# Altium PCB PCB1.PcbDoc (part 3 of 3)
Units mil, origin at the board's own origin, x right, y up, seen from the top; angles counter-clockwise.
Board outline 6299 x 3937 mil, 12 copper layers (TopLayer, VCC, GROUND, MidLayer1, MidLayer2, MidLayer3, MidLayer4, MidLayer5, MidLayer6, MidLayer7, MidLayer8, BottomLayer); 299 components, 467 nets, 2148 pads, 429 vias.
Unrouted connection lines stored in the file: 461.
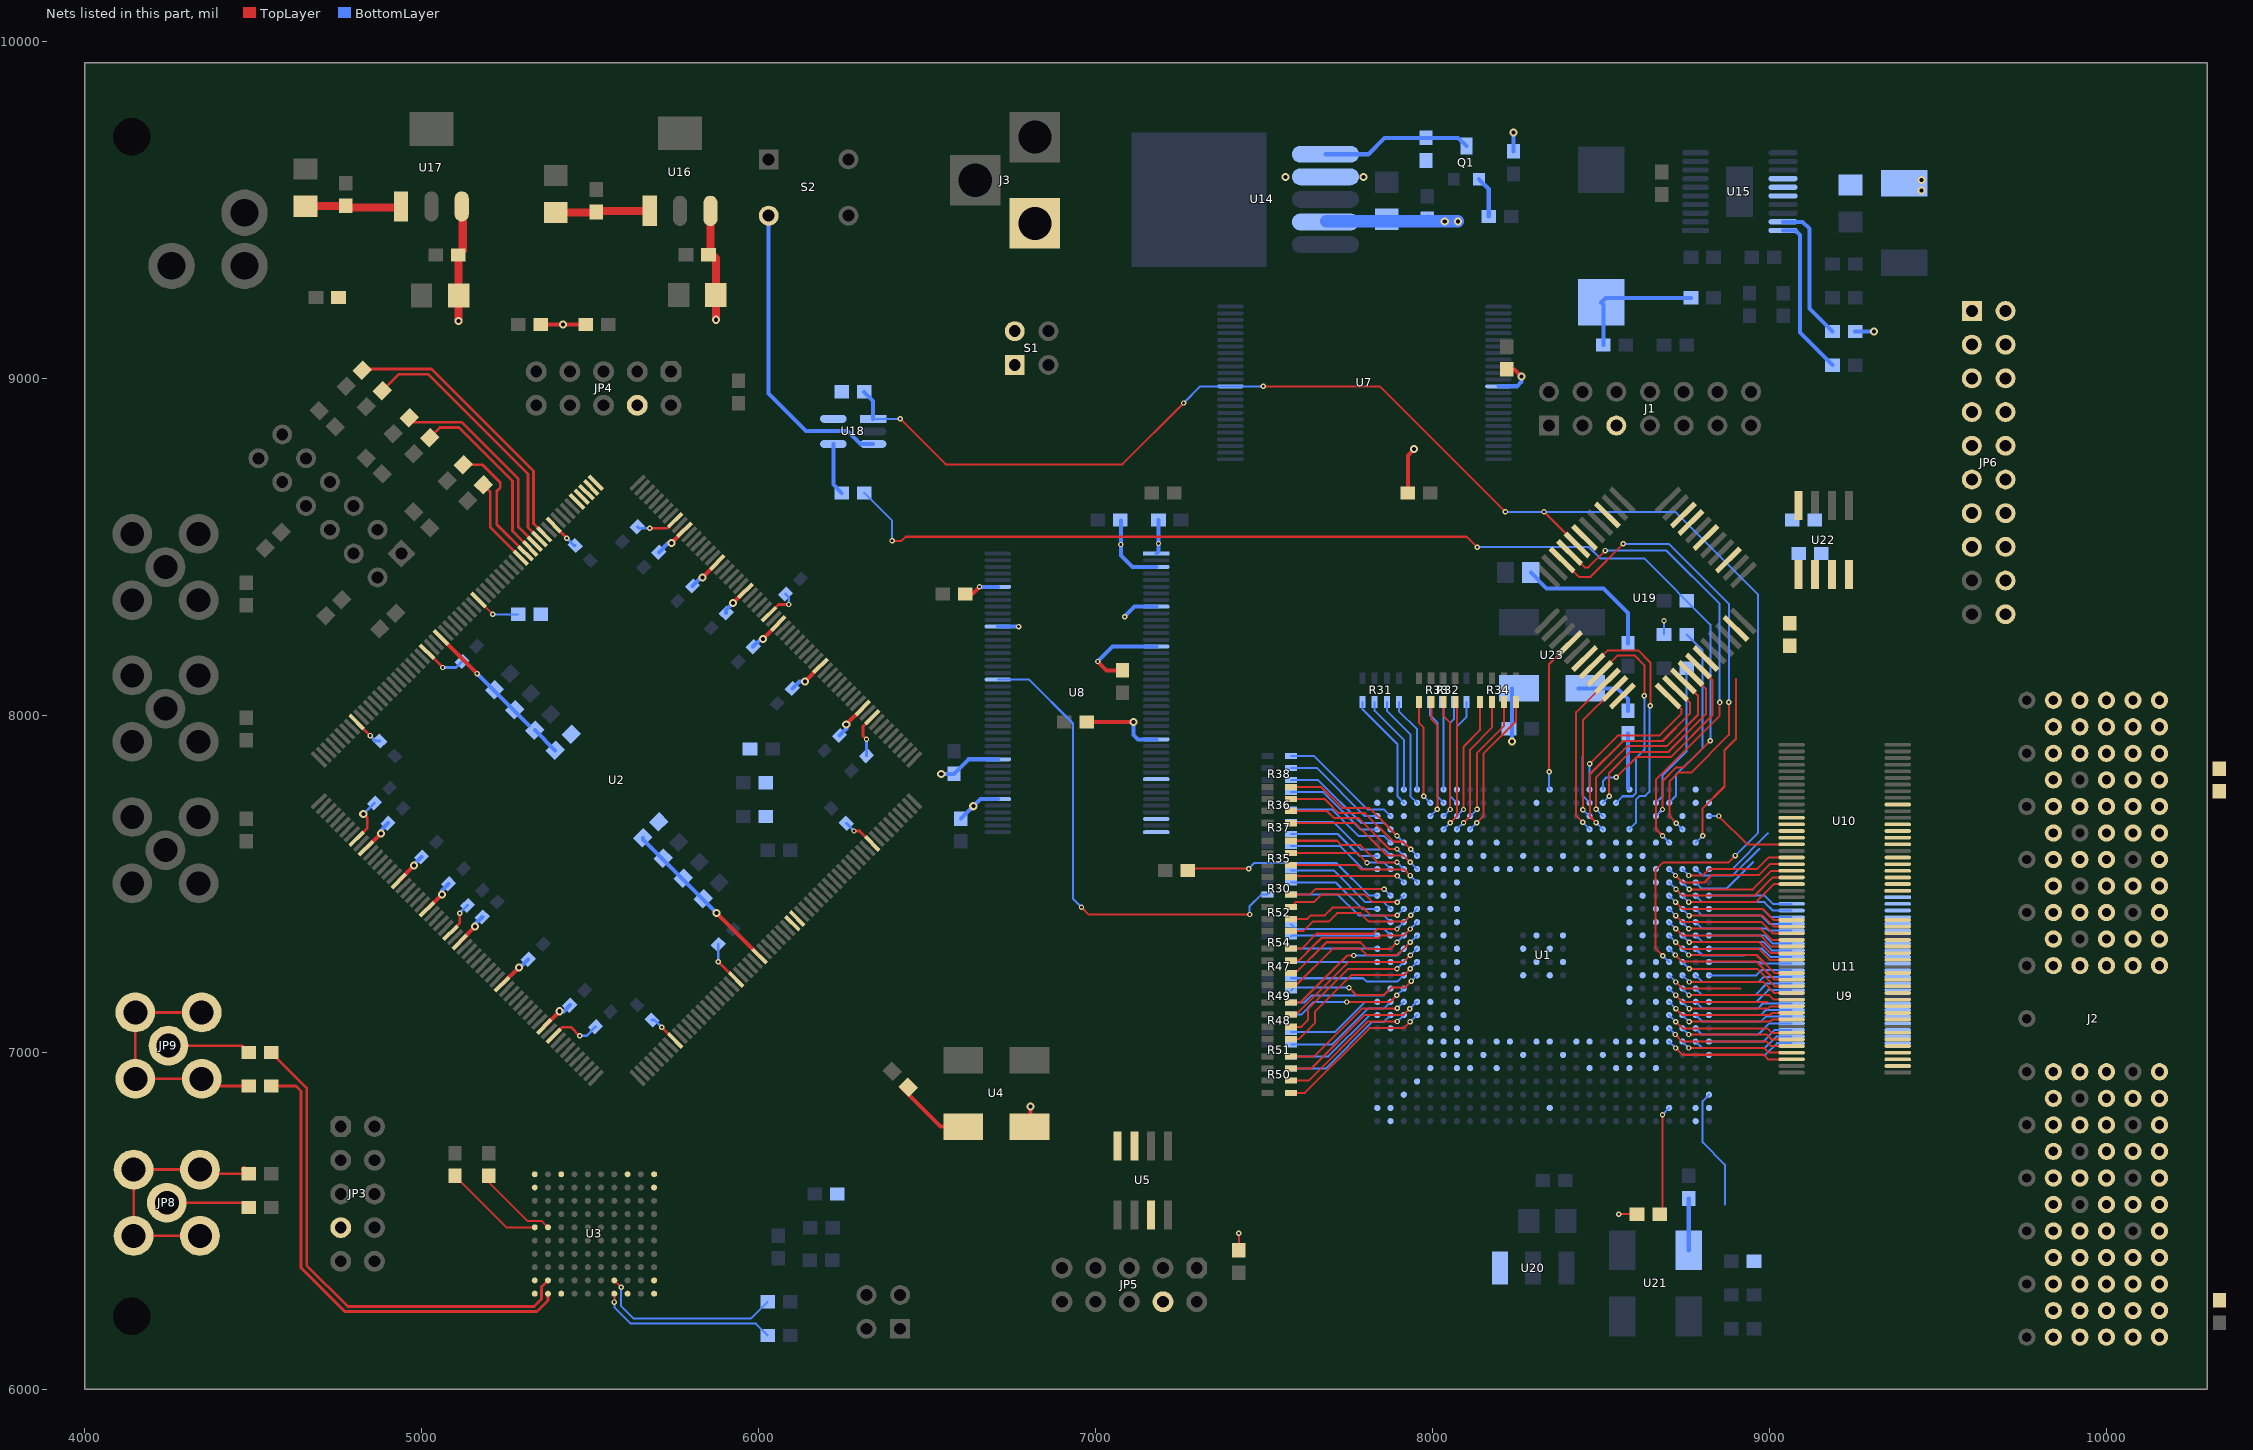
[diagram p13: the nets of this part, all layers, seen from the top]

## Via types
v1: diameter 16, hole 8, TopLayer to BottomLayer, 343 vias
v2: diameter 24, hole 12, TopLayer to BottomLayer, 84 vias
v3: diameter 56.69, hole 56.69, TopLayer to BottomLayer, 2 vias

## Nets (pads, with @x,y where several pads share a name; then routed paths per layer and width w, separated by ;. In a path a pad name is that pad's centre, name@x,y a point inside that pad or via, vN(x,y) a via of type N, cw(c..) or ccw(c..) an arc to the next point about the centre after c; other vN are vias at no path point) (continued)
NetDS3_2: DS3.2 R19.1
NetDS4_2: DS4.2 R20.1
NetDS5_2: DS5.2 R21.1
NetDS6_1: DS6.1 R62.1
NetDS7_1: DS7.1 R63.1
NetDS9_1: DS9.1 R86.2 | length 428.8
  BottomLayer w12: DS9.1@8291.4,8424 8338.4,8377 8507,8377 8580,8304 R86.2@8580,8213.46
NetQ1_1: Q1.1 R73.1 U14.1 | length 448.1
  BottomLayer w12: U14.1@7682,9665 7809,9665 7857.46,9713.46 8075.75,9713.46 Q1.1@8100,9689.21
NetQ1_2: Q1.2 R72.1 | length 124.8
  BottomLayer w12: Q1.2@8137.4,9590.79 8166.54,9561.65 R72.1@8166.54,9480 R72.1@8167.91,9481.37
NetR2_2: R2.2 U2.133 | length 781.9
  TopLayer w8: R2.2@4883.66,8963.66 4932,9012 5020,9012 5316,8716 5316,8557.18 U2.133@5350.03,8523.15
NetR3_2: R3.2 U2.132 | length 836.8
  TopLayer w8: R3.2@4823.66,9023.66 4828,9028 5029,9028 5332,8725 5332,8569.02 U2.132@5363.94,8537.07
NetR5_2: R5.2 U2.135 | length 546.1
  TopLayer w8: R5.2@5023.66,8823.66 5054,8854 5111,8854 5270,8695 5270,8547.5 U2.135@5322.19,8495.32
NetR6_2: R6.2 U2.134 | length 611.7
  TopLayer w8: R6.2@4963.66,8883.66 4977.33,8870 5119,8870 5287,8702 5287,8558.34 U2.134@5336.11,8509.24
NetR9_2: R9.2 U2.137 | length 262
  TopLayer w8: R9.2@5183.66,8683.66 5204,8663.33 5204,8557.82 U2.137@5294.35,8467.48
NetR10_2: R10.2 U2.136 | length 380.6
  TopLayer w8: R10.2@5123.66,8743.66 5181,8743.66 5233,8691.66 5233,8675 5223,8665 5223,8566.66 U2.136@5308.27,8481.4
NetR12_1: R12.1 U3.F9 | length 250.1
  TopLayer w6: R12.1@5199,6633.54 5199,6615 5315,6499 5356.89,6499 U3.F9@5375.04,6480.85
NetR13_1: R13.1 U3.F10 | length 299.9
  TopLayer w6: R13.1@5099,6633.54 5251.69,6480.85 U3.F10@5335.67,6480.85
NetR22_2: R22.2 U2.34
NetR23_2: R23.2 U2.35
NetR24_1: R24.1 U4.3 | length 231.7
  TopLayer w12: R24.1@6423.66,6896.34 6540,6780 U4.3@6607.15,6780
NetR25_1: R25.1 U6.3
NetR30_1: R30.1 U1.K25 | length 342.5
  BottomLayer w6: R30.1@7580,7540 7706.06,7540 7800.2,7445.87 7854.92,7445.87 U1.K25@7875.12,7425.67
NetR30_2: R30.2 U1.K26 | length 288.2
  BottomLayer w6: R30.2@7580,7504 7712.54,7504 7790.87,7425.67 U1.K26@7835.75,7425.67
NetR30_3: R30.3 U1.L25 | length 329
  BottomLayer w6: R30.3@7580,7468 7719.01,7468 7780.51,7406.5 7854.92,7406.5 U1.L25@7875.12,7386.3
NetR31_1: R31.1 U1.A23 | length 282.3
  BottomLayer w6: R31.1@7900,8040 7900,8012.4 7953.86,7958.54 U1.A23@7953.86,7780
NetR31_2: R31.2 U1.B23 | length 336.6
  BottomLayer w6: R31.2@7864,8040 7864,8013.95 7934.06,7943.9 7934.06,7760.43 U1.B23@7953.86,7740.63
NetR31_3: R31.3 U1.A24 | length 295.8
  BottomLayer w6: R31.3@7828,8040 7828,8013.54 7914.49,7927.05 U1.A24@7914.49,7780
NetR31_4: R31.4 U1.B24 | length 350.1
  BottomLayer w6: R31.4@7792,8040 7792,8018.04 7895.67,7914.37 7895.67,7759.45 U1.B24@7914.49,7740.63
NetR32_1: R32.1 U1.A20 | length 271.6
  BottomLayer w6: U1.A20@8071.97,7780 8071.97,7966.65 8100,7994.69 R32.1@8100,8040
NetR32_2: R32.2 U1.B20 | length 312.5
  BottomLayer w6: R32.2@8064,8040 8064,7990.18 8052.17,7978.35 8052.17,7760.43 U1.B20@8071.97,7740.63
NetR32_3: R32.3 U1.A21 | length 261.9
  BottomLayer w6: R32.3@8028,8040 8032.6,8035.4 U1.A21@8032.6,7780
NetR32_4: R32.4 U1.B21 | length 316.2
  BottomLayer w6: R32.4@7992,8040 7992,8001.11 8013.78,7979.33 8013.78,7759.45 U1.B21@8032.6,7740.63
NetR33_1: R33.1 U1.B22 | length 313.1
  TopLayer w6: R33.1@7960,8040 7960,7977.01 7973.43,7963.58 v1(7973.43,7760.43)
  BottomLayer w6: v1(7973.43,7760.43) U1.B22@7993.23,7740.63
NetR33_2: R33.2 U1.C22 | length 354.6
  TopLayer w6: R33.2@7996,8040 7996,7988.25 8013.78,7970.47 v1(8013.78,7721.81)
  BottomLayer w6: U1.C22@7993.23,7701.26 v1(8013.78,7721.81)
NetR33_3: R33.3 U1.C21 | length 355.2
  TopLayer w6: R33.3@8032,8040 8032,7998.51 8052.17,7978.35 v1(8052.17,7720.83)
  BottomLayer w6: U1.C21@8032.6,7701.26 v1(8052.17,7720.83)
NetR33_4: R33.4 U1.D21 | length 396
  TopLayer w6: v1(8052.17,7681.46) 8071.85,7701.14 8071.85,8036.15 R33.4@8068,8040
  BottomLayer w6: U1.D21@8032.6,7661.89 v1(8052.17,7681.46)
NetR34_1: R34.1 U1.C20 | length 366.9
  TopLayer w6: v1(8091.54,7720.83) 8091.54,7907.48 8140,7955.94 R34.1@8140,8040
  BottomLayer w6: U1.C20@8071.97,7701.26 v1(8091.54,7720.83)
NetR34_2: R34.2 U1.D20 | length 421.2
  TopLayer w6: v1(8091.54,7681.46) 8111.22,7701.14 8111.22,7898.62 8176,7963.4 R34.2@8176,8040
  BottomLayer w6: U1.D20@8071.97,7661.89 v1(8091.54,7681.46)
NetR34_3: R34.3 U1.C19 | length 380.4
  TopLayer w6: v1(8131.89,7721.81) 8131.89,7888.78 8212,7968.89 R34.3@8212,8040
  BottomLayer w6: U1.C19@8111.34,7701.26 v1(8131.89,7721.81)
NetR34_4: R34.4 U1.D19 | length 434.7
  TopLayer w6: v1(8130.91,7681.46) 8150.59,7701.14 8150.59,7885.83 8248,7983.24 R34.4@8248,8040
  BottomLayer w6: U1.D19@8111.34,7661.89 v1(8130.91,7681.46)
NetR35_1: R35.1 U1.H24 | length 343.9
  TopLayer w6: R35.1@7580,7520 7583.62,7523.62 v1(7895.27,7523.62)
  BottomLayer w6: v1(7895.27,7523.62) U1.H24@7914.49,7504.41
NetR35_2: R35.2 U1.H23 | length 395.2
  TopLayer w6: R35.2@7580,7556 7774.71,7556 7787.4,7543.31 7914.96,7543.31 v1(7933.66,7524.61)
  BottomLayer w6: v1(7933.66,7524.61) U1.H23@7953.86,7504.41
NetR35_3: R35.3 U1.G25 | length 315.1
  TopLayer w6: R35.3@7580,7592 7776.11,7592 v1(7805.12,7562.99)
  BottomLayer w6: v1(7805.12,7562.99) 7855.9,7562.99 U1.G25@7875.12,7543.78
NetR35_4: R35.4 U1.G24 | length 369.4
  TopLayer w6: R35.4@7580,7628 7716.49,7628 7729.33,7615.16 7785.43,7615.16 7836.61,7563.98 v1(7894.29,7563.98)
  BottomLayer w6: v1(7894.29,7563.98) U1.G24@7914.49,7543.78
NetR36_1: R36.1 U1.G23 | length 430.3
  TopLayer w6: R36.1@7580,7680 7769.8,7680 7866.14,7583.66 7913.98,7583.66 v1(7933.66,7563.98)
  BottomLayer w6: v1(7933.66,7563.98) U1.G23@7953.86,7543.78
NetR36_2: R36.2 U1.F24 | length 389.5
  TopLayer w6: R36.2@7580,7716 7686.56,7716 7707.52,7695.04 7780.36,7695.04 7872.05,7603.35 v1(7894.29,7603.35)
  BottomLayer w6: v1(7894.29,7603.35) U1.F24@7914.49,7583.15
NetR36_3: R36.3 U1.F23 | length 443.8
  TopLayer w6: R36.3@7580,7752 7679.1,7752 7721.46,7709.65 7799.21,7709.65 7883.86,7625 7912.01,7625 v1(7934.65,7602.36)
  BottomLayer w6: v1(7934.65,7602.36) U1.F23@7953.86,7583.15
NetR36_4: R36.4 U1.E24 | length 402.9
  TopLayer w6: R36.4@7580,7788 7668.69,7788 7723.97,7732.73 7731.38,7725.31 ; 7731.56,7725.49 7811.51,7725.49 v1(7894.29,7642.72)
  BottomLayer w6: v1(7894.29,7642.72) U1.E24@7914.49,7622.52
NetR37_1: R37.1 U1.E25 | length 335.5
  BottomLayer w6: R37.1@7580,7720 7702.24,7720 7780.51,7641.73 7855.9,7641.73 U1.E25@7875.12,7622.52
NetR37_2: R37.2 U1.F25 | length 336.9
  BottomLayer w6: R37.2@7580,7684 7704.78,7684 7786.42,7602.36 7855.9,7602.36 U1.F25@7875.12,7583.15
NetR37_3: R37.3 U1.F26 | length 282.6
  BottomLayer w6: R37.3@7580,7648 7718.14,7648 7782.99,7583.15 U1.F26@7835.75,7583.15
NetR37_4: R37.4 U1.G26 | length 284
  BottomLayer w6: R37.4@7580,7612 7725.6,7612 7793.82,7543.78 U1.G26@7835.75,7543.78
NetR38_1: R38.1 U1.C25 | length 369.2
  BottomLayer w6: R38.1@7580,7880 7647.56,7880 7807.09,7720.47 7855.9,7720.47 U1.C25@7875.12,7701.26
NetR38_2: R38.2 U1.C26 | length 314.9
  BottomLayer w6: R38.2@7580,7844 7656,7844 7798.74,7701.26 U1.C26@7835.75,7701.26
NetR38_3: R38.3 U1.D25 | length 355.6
  BottomLayer w6: R38.3@7580,7808 7660.5,7808 7787.4,7681.1 7855.9,7681.1 U1.D25@7875.12,7661.89
NetR38_4: R38.4 U1.D26 | length 301.4
  BottomLayer w6: R38.4@7580,7772 7675.83,7772 7785.94,7661.89 U1.D26@7835.75,7661.89
NetR39_1: R39.1 U19.21
NetR40_1: R40.1 U19.30
NetR47_1: R47.1 U1.M23 | length 450.2
  TopLayer w6: R47.1@7580,7200 7595.67,7200 7703.74,7308.07 7785.43,7308.07 7804.13,7289.37 7896.3,7289.37 v1(7933.7,7326.77)
  BottomLayer w6: v1(7933.7,7326.77) U1.M23@7953.86,7346.93
NetR47_2: R47.2 U1.M24 | length 397.6
  TopLayer w6: R47.2@7580,7236 7594.27,7236 7685.04,7326.77 7785.43,7326.77 7806.1,7306.1 7873.66,7306.1 v1(7894.33,7326.77)
  BottomLayer w6: v1(7894.33,7326.77) U1.M24@7914.49,7346.93
NetR47_3: R47.3 U1.L23 | length 421.2
  TopLayer w6: R47.3@7580,7272 7602.71,7272 7646.57,7315.86 7670.19,7339.48 7839.48,7339.48 7846.46,7346.46 7914.02,7346.46 v1(7933.7,7366.14)
  BottomLayer w6: v1(7933.7,7366.14) U1.L23@7953.86,7386.3
NetR47_4: R47.4 U1.L24 | length 366.9
  TopLayer w6: R47.4@7580,7308 7611.15,7308 7655.15,7352 7822,7352 7836.14,7366.14 v1(7894.33,7366.14)
  BottomLayer w6: v1(7894.33,7366.14) U1.L24@7914.49,7386.3
NetR48_1: R48.1 U1.P23 | length 488.6
  TopLayer w6: R48.1@7580,7040 7603.98,7040 7650.59,7086.61 7650.59,7121.06 7758.86,7229.33 7915,7229.33 v1(7933.7,7248.03)
  BottomLayer w6: v1(7933.7,7248.03) U1.P23@7953.86,7268.19
NetR48_2: R48.2 U1.P24 | length 433.1
  TopLayer w6: R48.2@7580,7076 7610.45,7076 7629.92,7095.47 7629.92,7127.95 7750,7248.03 v1(7894.33,7248.03)
  BottomLayer w6: v1(7894.33,7248.03) U1.P24@7914.49,7268.19
NetR48_3: R48.3 U1.N23 | length 454.2
  TopLayer w6: R48.3@7580,7112 7594.28,7112 7750.98,7268.7 7914.37,7268.7 v1(7934.06,7288.39)
  BottomLayer w6: v1(7934.06,7288.39) U1.N23@7953.23,7307.56
NetR48_4: R48.4 U1.N24 | length 400.6
  TopLayer w6: R48.4@7580,7148 7607.65,7148 7747.05,7287.4 v1(7765.75,7287.4)
  BottomLayer w6: v1(7765.75,7287.4) 7894.33,7287.4 U1.N24@7914.49,7307.56
NetR49_1: R49.1 U1.R24 | length 346.7
  BottomLayer w6: R49.1@7580,7220 7793.78,7220 7804.13,7209.65 7895.31,7209.65 U1.R24@7914.49,7228.82
NetR49_2: R49.2 U1.R23 | length 410.4
  TopLayer w6: v1(7751.97,7191.93) 7773.62,7170.28 7855.31,7170.28 7876.97,7191.93 7916.97,7191.93 v1(7936.65,7211.61)
  BottomLayer w6: R49.2@7580,7184 7587.93,7191.93 v1(7751.97,7191.93) ; v1(7936.65,7211.61) U1.R23@7953.86,7228.82
NetR49_3: R49.3 U1.T25 | length 312.3
  BottomLayer w6: R49.3@7580,7148 7619.46,7148 7640.75,7169.29 7854.96,7169.29 U1.T25@7875.12,7189.45
NetR49_4: R49.4 U1.T24 | length 372.8
  TopLayer w6: v1(7745.08,7149.61) 7874.02,7149.61 v1(7893.7,7169.29)
  BottomLayer w6: R49.4@7580,7112 7610.03,7112 7647.64,7149.61 v1(7745.08,7149.61) ; v1(7893.7,7169.29) 7913.86,7189.45 U1.T24@7920.75,7189.45
NetR50_1: R50.1 U1.V23 | length 469.4
  TopLayer w6: R50.1@7580,6880 7621.14,6880 7812.99,7071.85 7914.37,7071.85 v1(7933.07,7090.55)
  BottomLayer w6: v1(7933.07,7090.55) 7953.23,7110.71 U1.V23@7953.86,7110.71
NetR50_2: R50.2 U1.V24 | length 415.1
  TopLayer w6: R50.2@7580,6916 7632.54,6916 7808.07,7091.54 v1(7895.31,7091.54)
  BottomLayer w6: v1(7895.31,7091.54) U1.V24@7914.49,7110.71
NetR50_3: R50.3 U1.U23 | length 455.9
  TopLayer w6: R50.3@7580,6952 7639.01,6952 7798.23,7111.22 7913.39,7111.22 v1(7932.09,7129.92)
  BottomLayer w6: v1(7932.09,7129.92) 7952.24,7150.08 U1.U23@7953.86,7150.08
NetR50_4: R50.4 U1.U24 | length 401.6
  TopLayer w6: R50.4@7580,6988 7648.43,6988 7791.34,7130.91 v1(7895.31,7130.91)
  BottomLayer w6: v1(7895.31,7130.91) U1.U24@7914.49,7150.08
NetR51_1: R51.1 U1.U26 | length 293.1
  BottomLayer w6: R51.1@7580,7060 7709.61,7060 7799.68,7150.08 U1.U26@7835.75,7150.08
NetR51_2: R51.2 U1.U25 | length 347.3
  BottomLayer w6: R51.2@7580,7024 7702.15,7024 7808.07,7129.92 7854.96,7129.92 U1.U25@7875.12,7150.08
NetR51_3: R51.3 U1.V26 | length 306.6
  BottomLayer w6: R51.3@7580,6988 7690.76,6988 7813.46,7110.71 U1.V26@7835.75,7110.71
NetR51_4: R51.4 U1.V25 | length 360.9
  BottomLayer w6: R51.4@7580,6952 7682.31,6952 7820.87,7090.55 7854.96,7090.55 U1.V25@7875.12,7110.71
NetR52_1: R52.1 U1.K23 | length 421.9
  TopLayer w6: R52.1@7580,7360 7615.91,7360 7643.7,7387.8 7691.8,7387.8 7717,7413 7785.8,7413 7811,7387.8 7915.98,7387.8 v1(7934.68,7406.5)
  BottomLayer w6: v1(7934.68,7406.5) U1.K23@7953.86,7425.67
NetR52_2: R52.2 U1.K24 | length 366.2
  TopLayer w6: R52.2@7580,7396 7628.28,7396 7638.78,7406.5 7680.5,7406.5 7704,7430 7793.5,7430 7817,7406.5 v1(7895.31,7406.5)
  BottomLayer w6: v1(7895.31,7406.5) U1.K24@7914.49,7425.67
NetR52_3: R52.3 U1.J24 | length 366.5
  TopLayer w6: R52.3@7580,7432 7593.87,7445.87 7647,7445.87 7669.13,7468 7799.87,7468 7822,7445.87 v1(7895.31,7445.87)
  BottomLayer w6: v1(7895.31,7445.87) U1.J24@7914.49,7465.04
NetR52_4: R52.4 U1.J25 | length 309.8
  TopLayer w6: R52.4@7580,7468 7635.75,7468 7652,7484.25 v1(7855.9,7484.25)
  BottomLayer w6: v1(7855.9,7484.25) U1.J25@7875.12,7465.04
NetR54_1: R54.1 U1.M25 | length 308.8
  BottomLayer w6: R54.1@7580,7380 7593.86,7366.14 7855.9,7366.14 U1.M25@7875.12,7346.93
NetR54_2: R54.2 U1.M26 | length 257
  BottomLayer w6: R54.2@7580,7344 7582.93,7346.93 U1.M26@7835.75,7346.93
NetR54_3: R54.3 U1.N26 | length 255.9
  BottomLayer w6: R54.3@7580,7308 7580.44,7307.56 U1.N26@7835.75,7307.56
NetR54_4: R54.4 U1.P26 | length 257.3
  BottomLayer w6: R54.4@7580,7272 7583.81,7268.19 U1.P26@7835.75,7268.19
NetR55_1: R55.1 U1.J26 | length 611.5
  TopLayer w6: R55.1@7273.46,7540 7278.46,7545 v1(7454,7545)
  BottomLayer w6: v1(7454,7545) 7470.93,7561.93 7714.65,7561.93 7811.54,7465.04 U1.J26@7835.75,7465.04
NetR56_2: R56.2 S1.1
NetR57_2: R57.2 S1.2
NetR65_2: R65.2 U15.20 | length 481.9
  BottomLayer w12: U15.20@9039.84,9439 9076,9439 9090,9425 9090,9135.54 R65.2@9186.54,9039
NetR66_1: R66.1 U15.19 | length 420.1
  BottomLayer w12: U15.19@9039.84,9464.59 9097.41,9464.59 9118,9444 9118,9207.54 R66.1@9186.54,9139
NetR76_1: R76.1 U23.3 | length 194.9
  BottomLayer w12: U23.3@8432.85,8080 8548,8080 8580,8048 R76.1@8580,8013.46
NetR79_2: R79.2 U1.B4 | length 560.1
  BottomLayer w6: U1.B4@8701.89,7740.63 8722,7760.74 8722,7824 8801,7903 8801,8192.46 R79.2@8753.46,8240
NetR80_1: R80.1 U1.AE4 | length 326.9
  TopLayer w6: R80.1@8673.46,6520 8682,6528.54 v1(8682,6815.23)
  BottomLayer w6: v1(8682,6815.23) U1.AE4@8701.89,6835.12
NetR81_1: R81.1 U18.4 | length 155.4
  BottomLayer w12: U18.4@6221.89,8805.2 6221.89,8684.65 R81.1@6246.54,8660
NetR81_2: R81.2 R83.2 U1.C5 | length 3365.1
  TopLayer w6: v1(6396,8518) 6424,8518 6436,8530 8101,8530 v1(8132,8499) ; v1(8682,7720.74) 8682,7805 8722,7845 8744,7845 v1(8824,7925)
  BottomLayer w6: R81.2@6313.46,8660 6396,8577.46 v1(6396,8518) ; v1(8132,8499) 8464,8499 8497,8466 8627.46,8466 8824,8269.46 v1(8824,7925) ; U1.C5@8662.52,7701.26 v1(8682,7720.74)
NetR82_1: R82.1 U21.3 | length 153.7
  BottomLayer w12: U21.3@8760,6412.85 R82.1@8760,6566.54
NetR84_2: R84.2 U1.B5 | length 437
  BottomLayer w6: U1.B5@8662.52,7740.63 8682,7760.11 8682,7822 8753.46,7893.46 R84.2@8753.46,8140
NetS2_2: S2.2 U18.3 | length 899.7
  BottomLayer w12: S2.2@6030,9482.68 6030,8955 6141,8844 6264,8844 6302.8,8805.2 U18.3@6340,8805.2
NSTATUS: R29.1 U2.146 | length 134.9
  TopLayer w6: U2.146@5169.07,8342.2 v1(5211.27,8300)
  BottomLayer w6: v1(5211.27,8300) R29.1@5286.54,8300
OUT1+: C3.1 U3.B9 | length 1495.6
  TopLayer w8: C3.1@4553.46,7000 4659,6894.46 4659,6368 4781,6246 5334,6246 5356,6268 5356,6304.33 U3.B9@5375.04,6323.37
OUT1-: C4.1 U3.A9 | length 1439.3
  TopLayer w8: C4.1@4553.46,6900 4627,6900 4642,6885 4642,6361 4772,6231 5342,6231 5375.04,6264.04 U3.A9@5375.04,6284
OUT2+: C28.2 U3.A4 | length 529.4
  TopLayer w6: v1(5571.89,6259.11) U3.A4@5571.89,6284
  BottomLayer w6: v1(5571.89,6259.11) 5571.89,6244.11 5621,6195 5991.54,6195 C28.2@6026.54,6160
OUT2-: C27.2 U3.B4 | length 555.3
  TopLayer w6: U3.B4@5571.89,6323.37 v1(5592,6303.26)
  BottomLayer w6: v1(5592,6303.26) 5592,6247 5629.04,6209.96 5976.49,6209.96 C27.2@6026.54,6260
P\C\I\6\6\: R74.1 U1.AD1 | length 360.7
  BottomLayer w6: U1.AD1@8820,6874.49 8801,6855.49 8801,6733 8867,6667 8867,6549
P_AD0: U1.Y3 U9.45 | length 337.4
  TopLayer w6: v1(8760.23,7013) 8984,7013 8997.94,6999.06 U9.45@9065.04,6999.06
  BottomLayer w6: U1.Y3@8741.26,7031.97 v1(8760.23,7013)
P_AD1: U1.AA1 U11.25 | length 259.4
  BottomLayer w6: U1.AA1@8820,6992.6 8987.6,6992.6 9022.25,7027.24 U11.25@9065.04,7027.24
P_AD2: U1.Y4 U9.46 | length 384.9
  TopLayer w6: v1(8720.86,7013) 8740.86,6993 8982,6993 8995.63,6979.37 U9.46@9065.04,6979.37
  BottomLayer w6: U1.Y4@8701.89,7031.97 v1(8720.86,7013)
P_AD3: U1.Y2 U11.26 | length 306.3
  BottomLayer w6: U1.Y2@8780.63,7031.97 8799.6,7013 8986,7013 9019.93,7046.93 U11.26@9065.04,7046.93
P_AD4: U1.W3 U9.43 | length 337.4
  TopLayer w6: v1(8759.6,7053) 8991,7053 9005.58,7038.43 U9.43@9065.04,7038.43
  BottomLayer w6: U1.W3@8741.26,7071.34 v1(8759.6,7053)
P_AD5: U1.Y1 U11.27 | length 259.4
  BottomLayer w6: U1.Y1@8820,7031.97 8980.97,7031.97 9015.61,7066.61 U11.27@9065.04,7066.61
P_AD6: U1.W4 U9.44 | length 384.9
  TopLayer w6: v1(8720.23,7053) 8741.23,7032 8991,7032 9004.26,7018.74 U9.44@9065.04,7018.74
  BottomLayer w6: U1.W4@8701.89,7071.34 v1(8720.23,7053)
P_AD7: U1.W2 U11.28 | length 305.8
  BottomLayer w6: U1.W2@8780.63,7071.34 8798.97,7053 8966,7053 8999.3,7086.3 U11.28@9065.04,7086.3
P_AD8: U1.V2 U11.29 | length 298
  BottomLayer w6: U1.V2@8780.63,7110.71 8799.34,7092 8975,7092 8988.99,7105.98 U11.29@9065.04,7105.98
P_AD9: U1.V3 U9.40 | length 334.6
  TopLayer w6: v1(8760.97,7091) 9001,7091 9007.48,7097.48 U9.40@9065.04,7097.48
  BottomLayer w6: U1.V3@8741.26,7110.71 v1(8760.97,7091)
P_AD10: U1.V1 U11.30 | length 251.2
  BottomLayer w6: U1.V1@8820,7110.71 8973.71,7110.71 8988.67,7125.67 U11.30@9065.04,7125.67
P_AD11: U1.U4 U9.39 | length 381.9
  TopLayer w6: v1(8721.97,7130) 8740.97,7111 9001,7111 9007.17,7117.16 U9.39@9065.04,7117.16
  BottomLayer w6: U1.U4@8701.89,7150.08 v1(8721.97,7130)
P_AD12: U1.U2 U11.31 | length 299.1
  BottomLayer w6: U1.U2@8780.63,7150.08 8800.71,7130 8965,7130 8980.35,7145.35 U11.31@9065.04,7145.35
P_AD13: U1.U3 U9.38 | length 334.9
  TopLayer w6: v1(8761.34,7130) 8995,7130 9001.85,7136.85 U9.38@9065.04,7136.85
  BottomLayer w6: U1.U3@8741.26,7150.08 v1(8761.34,7130)
P_AD14: U1.U1 U11.33 | length 259.4
  BottomLayer w6: U1.U1@8820,7150.08 8961.08,7150.08 8995.73,7184.73 U11.33@9065.04,7184.73
P_AD15: U1.T3 U9.37 | length 337.4
  TopLayer w6: v1(8760.71,7170) 8999,7170 9012.47,7156.53 U9.37@9065.04,7156.53
  BottomLayer w6: U1.T3@8741.26,7189.45 v1(8760.71,7170)
P_AD16: U1.M3 U9.30 | length 345.6
  TopLayer w6: v1(8761.19,7327) 8970,7327 9002.67,7294.33 U9.30@9065.04,7294.33
  BottomLayer w6: U1.M3@8741.26,7346.93 v1(8761.19,7327)
P_AD17: U1.M2 U11.39 | length 302.7
  BottomLayer w6: U1.M2@8780.63,7346.93 8799.56,7328 8981,7328 9006.17,7302.84 U11.39@9065.04,7302.84
P_AD18: U1.M4 U9.31 | length 393.1
  TopLayer w6: v1(8721.82,7327) 8741.82,7307 8968,7307 9000.35,7274.65 U9.31@9065.04,7274.65
  BottomLayer w6: U1.M4@8701.89,7346.93 v1(8721.82,7327)
P_AD19: U1.L2 U11.42 | length 294.5
  BottomLayer w6: U1.L2@8780.63,7386.3 8798.93,7368 8990,7368 8996.11,7361.89 U11.42@9065.04,7361.89
P_AD20: U1.L3 U9.28 | length 345.6
  TopLayer w6: v1(8760.56,7367) 8973,7367 9006.3,7333.7 U9.28@9065.04,7333.7
  BottomLayer w6: U1.L3@8741.26,7386.3 v1(8760.56,7367)
P_AD21: U1.K2 U11.43 | length 302.7
  BottomLayer w6: U1.K2@8780.63,7425.67 8800.3,7406 8975,7406 8999.42,7381.57 U11.43@9065.04,7381.57
P_AD22: U1.L4 U9.29 | length 393.1
  TopLayer w6: v1(8721.19,7367) 8741.19,7347 8972,7347 9004.99,7314.02 U9.29@9065.04,7314.02
  BottomLayer w6: U1.L4@8701.89,7386.3 v1(8721.19,7367)
P_AD23: U1.K1 U11.44 | length 255.1
  BottomLayer w6: U1.K1@8820,7425.67 8978.33,7425.67 9002.74,7401.26 U11.44@9065.04,7401.26
P_AD24: U1.K4 U9.27 | length 393.1
  TopLayer w6: v1(8721.56,7406) 8740.56,7387 8975,7387 9008.61,7353.39 U9.27@9065.04,7353.39
  BottomLayer w6: U1.K4@8701.89,7425.67 v1(8721.56,7406)
P_AD25: U1.J1 U11.46 | length 255.2
  BottomLayer w6: U1.J1@8820,7465.04 8984.96,7465.04 9009.37,7440.63 U11.46@9065.04,7440.63
P_AD26: U1.J3 U10.46 | length 353.8
  TopLayer w6: v1(8760.3,7446) 8959,7446 9012.37,7499.37 U10.46@9065.04,7499.37
  BottomLayer w6: U1.J3@8741.26,7465.04 v1(8760.3,7446)
P_AD27: U1.H2 U10.36 | length 210.7
  BottomLayer w6: U1.H2@8780.63,7504.41 8799.04,7486 8872,7486 8951,7565
P_AD28: U1.J4 U9.25 | length 393.1
  TopLayer w6: v1(8720.93,7446) 8740.93,7426 8979,7426 9012.25,7392.76 U9.25@9065.04,7392.76
  BottomLayer w6: U1.J4@8701.89,7465.04 v1(8720.93,7446)
P_AD29: U1.G2 U10.37 | length 229.9
  BottomLayer w6: U1.G2@8780.63,7543.78 8799.41,7525 8891,7525 8970,7604
P_AD30: U1.H3 U10.44 | length 354.9
  TopLayer w6: v1(8761.67,7484) 8950,7484 9004.74,7538.74 U10.44@9065.04,7538.74
  BottomLayer w6: U1.H3@8741.26,7504.41 v1(8761.67,7484)
P_AD31: U1.G1 U10.38 | length 219
  BottomLayer w6: U1.G1@8820,7543.78 8888.78,7543.78 8995,7650
P_CBE0: U1.V4 U9.42 | length 384.9
  TopLayer w6: v1(8721.6,7091) 8741.6,7071 8993,7071 9005.89,7058.11 U9.42@9065.04,7058.11
  BottomLayer w6: U1.V4@8701.89,7110.71 v1(8721.6,7091)
P_CBE1: U1.T2 U11.34 | length 306.7
  BottomLayer w6: U1.T2@8780.63,7189.45 8800.08,7170 8957,7170 8991.41,7204.41 U11.34@9065.04,7204.41
P_CBE2: U1.M1 U11.40 | length 255.1
  BottomLayer w6: U1.M1@8820,7346.93 8985.07,7346.93 9009.48,7322.52 U11.40@9065.04,7322.52
P_CBE3: U1.J2 U11.45 | length 302.7
  BottomLayer w6: U1.J2@8780.63,7465.04 8799.67,7446 8984,7446 9009.06,7420.94 U11.45@9065.04,7420.94
P_CLK: U1.C1 U10.40 | length 279.7
  TopLayer w6: v1(8849.26,7701.26) 8933.04,7617.48 U10.40@9065.04,7617.48
  BottomLayer w6: U1.C1@8820,7701.26 v1(8849.26,7701.26)
P_DEVSEL: U1.P1 U11.37 | length 247
  BottomLayer w6: U1.P1@8820,7268.19 8971,7268.19 8975.72,7263.47 U11.37@9065.04,7263.47
P_EN: R61.1 U1.E2 | length 534.9
  TopLayer w6: v1(8801.11,7643) 8801.11,7724.11 8866,7789 8866,7896 8900,7930 8900,8108
  BottomLayer w6: U1.E2@8780.63,7622.52 v1(8801.11,7643)
P_FRAME: U1.N4 U9.34 | length 401.2
  TopLayer w6: v1(8720.45,7289) 8740.45,7269 8961,7269 9014.41,7215.59 U9.34@9065.04,7215.59
  BottomLayer w6: U1.N4@8701.89,7307.56 v1(8720.45,7289)
P_GNT: U1.H4 U10.45 | length 401.9
  TopLayer w6: v1(8722.3,7484) 8741.3,7465 8955,7465 9009.06,7519.06 U10.45@9065.04,7519.06
  BottomLayer w6: U1.H4@8701.89,7504.41 v1(8722.3,7484)
P_IDSEL: U1.K3 U9.26 | length 345.6
  TopLayer w6: v1(8760.93,7406) 8979,7406 9011.93,7373.07 U9.26@9065.04,7373.07
  BottomLayer w6: U1.K3@8741.26,7425.67 v1(8760.93,7406)
P_INTA: U1.G4 U10.43 | length 402.2
  TopLayer w6: v1(8720.67,7525) 8741.67,7504 8806,7504 8828.93,7526.93 8968.93,7526.93 9000.42,7558.43 U10.43@9065.04,7558.43
  BottomLayer w6: U1.G4@8701.89,7543.78 v1(8720.67,7525)
P_IRDY: U1.N1 U11.38 | length 255.1
  BottomLayer w6: U1.N1@8820,7307.56 8977.44,7307.56 9001.85,7283.15 U11.38@9065.04,7283.15
P_PAR: U1.P3 U9.35 | length 353.7
  TopLayer w6: v1(8761.45,7248) 8963,7248 9015.09,7195.9 U9.35@9065.04,7195.9
  BottomLayer w6: U1.P3@8741.26,7268.19 v1(8761.45,7248)
P_PERR: U1.R1 U11.36 | length 251.2
  BottomLayer w6: U1.R1@8820,7228.82 8960.82,7228.82 8975.78,7243.78 U11.36@9065.04,7243.78
P_REQ: U1.F1 U10.39
P_RST: U1.G3 U10.42 | length 353.6
  TopLayer w6: v1(8760.04,7525) 8802,7525 8821,7544 8962,7544 8996.11,7578.11 U10.42@9065.04,7578.11
  BottomLayer w6: U1.G3@8741.26,7543.78 v1(8760.04,7525)
P_SERR: U1.R2 U11.35 | length 298.9
  BottomLayer w6: U1.R2@8780.63,7228.82 8800.45,7209 8968,7209 8983.09,7224.1 U11.35@9065.04,7224.1
P_STOP: U1.R3 U9.36 | length 345.6
  TopLayer w6: v1(8761.08,7209) 8981,7209 9013.78,7176.22 U9.36@9065.04,7176.22
  BottomLayer w6: U1.R3@8741.26,7228.82 v1(8761.08,7209)
P_TRDY: U1.N3 U9.33 | length 353.7
  TopLayer w6: v1(8759.82,7289) 8961,7289 9014.73,7235.27 U9.33@9065.04,7235.27
  BottomLayer w6: U1.N3@8741.26,7307.56 v1(8759.82,7289)
PCI_EEAI: R78.1 U1.L5
PXI_3.3V: J2.B25 J2.C6 J2.C10 J2.C18 J2.C22 J2.E15 J2.E17 J2.E19 J2.E21 J2.E23
PXI_5V: J2.A1 J2.A25 J2.B3 J2.B23 J2.D2 J2.D24 J2.E1 J2.E25
PXI_+12V: J2.B1
PXI_-12V: J2.D1
PXI_ACK64#: J2.A24 JP6.9
PXI_AD0: J2.B24 U9.3
PXI_AD1: J2.E24 U11.24
PXI_AD2: J2.A23 U9.2
PXI_AD3: J2.C23 U11.23
PXI_AD4: J2.D23 U9.5
PXI_AD5: J2.A22 U11.22
PXI_AD6: J2.B22 U9.4
PXI_AD7: J2.E22 U11.21
PXI_AD8: J2.C21 U11.20
PXI_AD9: J2.D21 U9.7
PXI_AD10: J2.A20 U11.19
PXI_AD11: J2.B20 U9.9
PXI_AD12: J2.E20 U11.18
PXI_AD13: J2.A19 U9.10
PXI_AD14: J2.C19 U11.16
PXI_AD15: J2.D19 U9.11
PXI_AD16: J2.C11 U9.19
PXI_AD17: J2.D11 U11.9
PXI_AD18: J2.E11 U9.18
PXI_AD19: J2.A10 U11.6
PXI_AD20: J2.B10 U9.21
PXI_AD21: J2.E10 U11.5
PXI_AD22: J2.A9 U9.20
PXI_AD23: J2.C9 U11.4
PXI_AD24: J2.A8 U9.22
PXI_AD25: J2.B8 U11.2
PXI_AD26: J2.E8 U10.2
PXI_AD27: J2.A7 U10.12
PXI_AD28: J2.C7 U9.24
PXI_AD29: J2.D7 U10.11
PXI_AD30: J2.E7 U10.4
PXI_AD31: J2.A6 U10.10
PXI_BD_SEL#: J2.B15 JP6.5
PXI_BRSVP1A5: J2.E5
PXI_BRSVP1A6: JP6.2
PXI_BRSVP1B5: J2.D5
PXI_BRSVP1B6: JP6.12
PXI_C/BE0#: J2.A21 U9.6
PXI_C/BE1#: J2.A18 U11.14
PXI_C/BE2#: J2.A11 U11.7
PXI_C/BE3#: J2.E9 U11.3
PXI_DEVSEL#: J2.E16 U11.11
PXI_ENUM#: J2.C25 JP6.15
PXI_FRAME#: J2.D15 U9.14
PXI_GNT#: J2.A5 U10.3
PXI_HEALTHY#: J2.C1 J2.D4 JP6.14
PXI_IDSEL: J2.D9 U9.23
PXI_INTA#: J2.E3 U10.5
PXI_INTB#: J2.D3 JP6.16
PXI_INTC#: J2.C3 JP6.20
PXI_INTD#: J2.A3 JP6.13
PXI_INTP: J2.B4 JP6.3
PXI_INTS: J2.A4 JP6.11
PXI_IPMB_PWR: J2.E4 JP6.4
PXI_IPMB_SCL: J2.D17 JP6.10
PXI_IPMB_SDA: J2.C17 JP6.18
PXI_IRDY#: J2.C15 U11.10
PXI_LOCK#: J2.A16
PXI_M66EN: J2.B21 JP6.7 R60.2
PXI_PAR: J2.B18 U9.13
PXI_PCLK: J2.B6 U10.7
PXI_PERR#: J2.A17 U11.12
PXI_REQ64#: J2.D25 JP6.8
PXI_REQ#: J2.E6 U10.9
PXI_RST#: J2.C5 U10.6
PXI_SERR#: J2.E18 U11.13
PXI_STOP#: J2.B16 U9.12
PXI_TCK: J2.E2 JP6.6
PXI_TDIO: J2.A2 J2.B2
PXI_TMS: J2.C2 JP6.1
PXI_TRDY#: J2.A15 U9.16
PXI_VIO: J2.C4 J2.C8 J2.C16 J2.C20 J2.C24
SCL: R87.2 U1.E4 U19.41 | length 1352.2
  TopLayer w6: U19.41@8406.81,8483.22 8451.04,8439 8462,8439 v1(8512,8489) ; v1(8682,7642.41) 8663,7661.41 8663,7810 8851.61,7998.61 v1(8851.61,8038.42)
  BottomLayer w6: v1(8512,8489) 8694,8489 8851.61,8331.39 v1(8851.61,8038.42) ; v1(8682,7642.41) U1.E4@8701.89,7622.52
SDA: R88.2 U1.D3 U19.42 | length 1410.4
  TopLayer w6: U19.42@8384.54,8460.95 8435.49,8410 8467,8410 v1(8566,8509) ; v1(8723,7680.15) 8703,7700.15 8703,7804 8729,7830 8767,7830 8879,7942 v1(8879,8039)
  BottomLayer w6: v1(8566,8509) 8701,8509 8879,8331 v1(8879,8039) ; v1(8723,7680.15) U1.D3@8741.26,7661.89
SDCKE: R30.6 U8.67 | length 1432.1
  TopLayer w6: v1(6958,7431) 6980,7409 v1(7457,7409)
  BottomLayer w6: U8.67@6710,8105.98 6803.02,8105.98 6933,7976 6933,7456 v1(6958,7431) ; v1(7457,7409) 7457.25,7434.25 7491,7468 R30.6@7509.84,7468
SERIN+: C2.2 JP8.1 | length 248.3
  TopLayer w8: JP8.1@4244,6554 4472.54,6554 C2.2@4486.54,6540
SERIN-: C1.2 JP8.2 | length 757.4
  TopLayer w8: JP8.2@4342.43,6455.57 JP8.2@4145.57,6455.57 JP8.2@4145.57,6652.43 JP8.2@4342.43,6652.43 4354.85,6640 C1.2@4486.54,6640
  TopLayer w20: C1.2@4474.11,6652.43 C1.2@4486.54,6640
SEROUT+: C3.2 JP9.1 | length 245.8
  TopLayer w8: JP9.1@4249,7020 4466.54,7020 C3.2@4486.54,7000
SEROUT-: C4.2 JP9.2 | length 769.1
  TopLayer w8: JP9.2@4347.43,7118.43 JP9.2@4150.57,7118.43 JP9.2@4150.57,6921.57 JP9.2@4347.43,6921.57 4369,6900 C4.2@4486.54,6900
  TopLayer w20: JP9.2@4347.43,6921.57 JP9.2@4369,6900
SYSTEM_RESET#: R71.1 U1.P4 U7.12 U18.1 U19.40 | length 4610.2
  TopLayer w6: v1(6420,8880) 6555,8745 7079,8745 v1(7261,8927) ; v1(7497.47,8976.53) 7843.47,8976.53 v1(8216,8604) ; v1(8330.58,8604) U19.40@8429.08,8505.49 ; v1(8683,7287.08) 8662,7308.08 8662,7542 8683,7563 8877,7563 v1(8898,7584)
  BottomLayer w6: U18.1@6340,8880 v1(6420,8880) ; v1(7261,8927) 7310.53,8976.53 v1(7497.47,8976.53) ; v1(8216,8604) 8720,8604 8966,8358 8966,7652 v1(8898,7584) ; v1(8683,7287.08) U1.P4@8701.89,7268.19
  BottomLayer w12: R71.1@6313.46,8960 6340,8933.46 U18.1@6340,8880
USER_LED0: DS1.1 U2.125
USER_LED1: DS2.1 U2.124
USER_LED2: DS3.1 U2.123
USER_LED3: DS4.1 U2.122
USER_LED4: DS5.1 U2.121
V1.4: C42.1 C43.1 C44.1 C50.1 C51.1 C52.1 C53.1 C60.1 C61.1 C62.1 C63.2 C70.1 C71.1 C72.1 C78.2 C79.1 C80.1 C81.1 C87.1 C88.1 C89.1 C90.2 C91.2 C92.2 C93.2 C94.2 C126.2 C138.1 C145.1 C148.1 C149.1 C151.1 L1.2 R69.2 R70.2 U1.AA6 U1.AA7 U1.AA20 U1.AA21 U1.F6 U1.F7 U1.F20 U1.F21 U1.G6 U1.G7 U1.G8 U1.G10 U1.G11 U1.G13 U1.G14 U1.G16 U1.G17 U1.G19 U1.G20 U1.G21 U1.H7 U1.H20 U1.K7 U1.K20 U1.L7 U1.L20 U1.M12 U1.M14 U1.N7 U1.N13 U1.N15 U1.N20 U1.P7 U1.P12 U1.P14 U1.P20 U1.R13 U1.R15 U1.T7 U1.T20 U1.U7 U1.U20 U1.W20 U1.Y6 U1.Y7 U1.Y8 U1.Y10 U1.Y11 U1.Y13 U1.Y14 U1.Y16 U1.Y17 U1.Y19 U1.Y20 U1.Y21 | length 401.2
  BottomLayer w12: R69.2@8506.54,9099 8506.54,9218.76 L1.2@8500,9225.3 8513.7,9239 R70.2@8766.54,9239
V1.5: C100.1 C101.1 C106.1 C107.1 C111.1 C112.1 C116.1 C117.1 C120.1 C121.1 C123.1 C124.1 C125.2 C137.1 FB1.1 FB2.1 U2.72 U2.81 U2.90 U2.97 U2.103 U2.110 U2.191 U2.198 U2.204 U2.211 U2.220 U2.229 U16.3 | length 1566.6
  TopLayer w12: U2.191@4835.01,7605.86 v2(4879,7649.86) ; U2.198@4932.44,7508.43 v2(4978,7553.99) ; U2.204@5015.96,7424.91 v2(5060,7468.95) ; U2.211@5113.4,7327.48 v2(5159,7373.08) ; U2.220@5238.67,7202.2 v2(5288.47,7252) ; U2.229@5363.94,7076.93 v2(5409.02,7122) ; v2(5741,8511.86) U2.110@5780.14,8550.99 ; v2(5833.01,8409) U2.103@5877.57,8453.56 ; v2(5924,8332.95) U2.97@5961.09,8370.04 ; v2(6012.92,8227) U2.90@6058.52,8272.6 ; v2(6137.47,8101) U2.81@6183.8,8147.33 ; v2(6260,7972.98) U2.72@6309.07,8022.06
  TopLayer w24: U16.3@5857,9497 5857,9372.54 5873.12,9356.42 v2(5873.12,9173.88)
  BottomLayer w12: v2(4879,7649.86) 4879,7659 C100.1@4900,7680 ; v2(4978,7553.99) 4978,7558 C106.1@5000,7580 ; v2(5060,7468.95) 5060,7480 C111.1@5080,7500 ; v2(5159,7373.08) 5159,7381 C116.1@5180,7402 ; v2(5288.47,7252) 5292,7252 C123.1@5316.16,7276.16 ; v2(5409.02,7122) 5422,7122 C120.1@5440,7140 ; C124.1@5703.84,8483.84 5731.86,8511.86 v2(5741,8511.86) ; C112.1@5803.84,8383.84 5829,8409 v2(5833.01,8409) ; C101.1@5903.84,8303.84 5903.84,8312.79 v2(5924,8332.95) ; C121.1@5983.84,8203.84 6007,8227 v2(6012.92,8227) ; C117.1@6100,8080 6121,8101 v2(6137.47,8101) ; C107.1@6240,7940 6260,7960 v2(6260,7972.98)
V2.5: C97.1 C103.1 C108.1 C132.2 C143.1 U2.130 U2.157 U2.172 U17.3 | length 656.5
  TopLayer w8: U2.172@4807.17,7980.3 v1(4847.46,7940) ; U2.157@5015.96,8189.04 v1(5063,8142) ; U2.130@5391.78,8564.91 v1(5430.7,8526)
  TopLayer w24: v2(5110.12,9169.88) 5110.12,9364.35 C132.2@5108.46,9366 5122,9379.54 U17.3@5122,9507
  BottomLayer w8: v1(4847.46,7940) 4863.62,7923.84 C108.1@4876.16,7923.84 ; v1(5063,8142) 5102,8142 C103.1@5120,8160 ; v1(5430.7,8526) 5452.86,8503.84 C97.1@5456.16,8503.84
V3.3: C5.2 C6.2 C7.2 C8.2 C9.2 C10.2 C11.2 C12.2 C13.2 C14.2 C15.2 C16.2 C17.2 C18.2 C19.2 C20.2 C21.2 C22.2 C23.2 C24.2 C25.2 C26.2 C37.1 C38.1 C39.1 C40.1 C41.1 C45.1 C46.1 C47.1 C48.1 C49.1 C55.1 C56.1 C57.1 C58.1 C59.1 C65.1 C66.1 C67.1 C68.1 C69.1 C73.1 C74.1 C75.1 C76.1 C77.1 C82.1 C83.1 C84.1 C85.1 C86.1 C95.2 C98.1 C99.1 C104.1 C105.1 C109.1 C110.1 C114.1 C115.1 C119.1 C133.2 C135.1 C144.1 C147.1 C150.1 C152.1 C154.2 C156.2 C158.2 C162.2 C165.2 FB3.1 J1.5 JP3.7 JP4.4 JP5.4 R8.2 R14.2 R16.2 R26.2 R27.2 R29.2 R56.1 R57.1 R58.2 R61.2 R63.2 R71.2 R74.2 R78.2 R79.1 R80.2 R87.1 R88.1 U1.A2 U1.A25 U1.AA9 U1.AA12 U1.AA15 U1.AA18 U1.AB5 U1.AB7 U1.AB8 U1.AB10 U1.AB17 U1.AB19 U1.AB20 U1.AB22 U1.AC23 U1.AD24 U1.AE1 U1.AE2 U1.AE13 U1.AE25 U1.AE26 U1.AF2 U1.AF25 U1.B1 U1.B2 U1.B14 U1.B25 U1.B26 U1.C3 U1.C24 U1.D4 U1.D23 U1.E5 U1.E7 U1.E8 U1.E10 U1.E17 U1.E19 U1.E20 U1.E22 U1.F9 U1.F12 U1.F15 U1.F18 U1.G5 U1.G22 U1.H5 U1.H22 U1.J6 U1.J21 U1.K5 U1.K22 U1.M6 U1.M21 U1.N2 U1.P25 U1.R6 U1.R21 U1.U5 U1.U22 U1.V21 U1.W5 U1.W22 U1.W25 U1.Y5 U1.Y22 U2.9 U2.22 U2.51 U2.70 U2.92 U2.112 U2.189 U2.209 U2.231 U3.A1 U3.A3 U3.A8 U3.A10 U3.B1 U3.B10 U3.J1 U3.J10 U3.K1 U3.K3 U3.K8 U3.K10 U4.4 U5.3 U5.7 U5.8 U6.4 U7.37 U8.1 U8.3 U8.9 U8.15 U8.29 U8.35 U8.41 U8.43 U8.49 U8.55 U8.75 U8.81 U14.4 U18.5 U19.6 U19.17 U19.39 U20.1 U22.8 U23.4 | length 3840.8
  TopLayer w6: R26.2@7425,6413.46 v1(7425,6463) ; v1(8552,6520) R80.2@8606.54,6520
  TopLayer w8: U2.189@4807.17,7633.7 4839,7665.54 4839,7695 v2(4827,7707) ; U2.209@5085.56,7355.31 5113,7382.76 v1(5113,7413) ; U2.231@5391.78,7049.09 5417.7,7075 5443,7075 v1(5469,7049) ; v1(5677,8555) 5728.46,8555 U2.112@5752.3,8578.83 ; v1(5713,7074.46) U2.9@5752.3,7035.17 ; v1(5880,7269.37) U2.22@5933.25,7216.12 ; U2.92@6030.69,8300.44 6059.24,8329 v1(6089,8329) ; v1(6283,7657) 6299.7,7657 U2.51@6336.91,7619.78 ; v1(6320,7929) 6310,7939 6310,7967.3 U2.70@6336.91,7994.22
  TopLayer w12: R14.2@5353.46,9160 R16.2@5486.54,9160 ; C20.2@6613.46,8360 6634,8360 v1(6655.57,8381.58) ; U4.4@6807,6782 v2(6807,6839) ; C26.2@6973.46,7980 v2(7113,7980) ; v1(7006,8160) 7032.54,8133.46 C25.2@7080,8133.46 ; R58.2@7926.54,8660 7926.54,8771.54 v2(7945,8790) ; C19.2@8220,9026.54 8242.46,9026.54 v2(8264,9005)
  BottomLayer w6: R79.1@8686.54,8240 v1(8686.54,8280.46)
  BottomLayer w8: v2(4827,7707) C98.1@4860,7740 ; v1(5113,7413) C99.1@5136.16,7436.16 ; v1(5469,7049) 5489,7049 C105.1@5516.16,7076.16 ; C119.1@5640,8560 5645,8555 v1(5677,8555) ; C104.1@5683.84,7096.16 5691.31,7096.16 v1(5713,7074.46) ; v1(5880,7269.37) C115.1@5880,7320 ; C114.1@6080,8360 6089,8351 v1(6089,8329) ; C109.1@6260,7680 v1(6283,7657) ; C110.1@6320,7880 v1(6320,7929) ; U1.N2@8780.63,7307.56 8800.19,7288 8924,7288
  BottomLayer w12: v2(6542,7826) C21.2@6580,7826.54 6623.23,7869.77 U8.55@6710,7869.77 ; C22.2@6600,7693.46 6658.19,7751.65 U8.49@6710,7751.65 ; v1(6655.57,8381.58) U8.81@6710,8381.58 ; U8.75@6710,8263.47 v1(6771.47,8263.47) ; v1(7006,8160) 7050.41,8204.41 U8.15@7180,8204.41 ; C24.2@7075,8578.46 7075,8475 7109.37,8440.63 U8.3@7180,8440.63 ; v1(7086,8293) 7115.52,8322.52 U8.9@7180,8322.52 ; v2@7113,7972 7113,7942 7126.18,7928.82 U8.29@7180,7928.82 ; U8.1@7180,8480 7186.54,8486.54 C23.2@7186.54,8580 ; U7.37@8195.28,8976.53 8250.53,8976.53 8264,8990 v2(8264,9005) ; v2(8236,7922) U23.4@8236,8080
  BottomLayer w24: C95.2@7976.46,9466 C95.2@7984,9473.54
  BottomLayer w36: U14.4@7684,9466 7858.12,9466 7976.46,9466 v2(8075,9466)
  other v1: 7075,8507 7186.54,8510
  other v2: 6636.98,7730.45 5420,9160 8036,9466
V3.3A: C153.2 C155.2 C157.2 C159.2 U19.25 U19.28 U19.31 U19.36
V5: C32.2 C36.2 C96.2 C127.2 C134.1 C136.1 C139.1 C140.1 C146.1 C166.2 J3.1 R62.2 R64.1 R66.2 R73.2 U9.15 U10.15 U11.15 U14.2 U15.14 U15.15 U15.16 U16.1 U17.1 | length 682.8
  TopLayer w24: C139.1@4655,9510.88 4773.35,9510.88 4777.23,9507 U17.1@4942,9507 ; C136.1@5398,9491.88 5516.35,9491.88 5521.46,9497 U16.1@5677,9497
  BottomLayer w12: R64.1@8240,9673.46 v2(8240,9730) ; R66.2@9253.46,9139 v2(9310,9139)
  other v2: 9451,9558 9450,9588 7564,9597 7795,9597
VCCA_PLL1: C128.2 C130.2 C141.1 FB1.2 U2.27 | length 498.3
  TopLayer w12: v2(5875.56,7413) U2.27@6002.85,7285.72
  BottomLayer w12: FB1.2@5656.34,7636.34 5656.34,7632.23 v2(5875.56,7413) v2@5875.56,7417.11
VCCA_PLL2: C129.2 C131.2 C142.1 FB2.2 U2.154 | length 453.7
  TopLayer w12: U2.154@5057.72,8230.85 v1(5164.56,8124)
  BottomLayer w12: v1(5164.56,8124) 5318.56,7970 ; C142.1@5336.34,7956.34 FB2.2@5396.34,7896.34
VP0_27MHZ: R76.2 U1.A7 | length 168.1
  BottomLayer w6: U1.A7@8580,7783.78 U1.A7@8583.78,7780
  BottomLayer w12: U1.A7@8580,7783.78 R76.2@8580,7946.54
VP0_CLK1: U1.A13 U19.4 | length 459
  TopLayer w6: v1(8346,7833) 8346,8152.37 U19.4@8406.81,8213.19
  BottomLayer w6: v1(8346,7833) 8346,7781.56 U1.A13@8347.56,7780
VP0_HSYNC: U1.B8 U19.8 | length 627.1
  TopLayer w6: U19.8@8495.9,8124.1 8549.8,8178 8599,8178 8628,8149 v1(8628,8058)
  BottomLayer w6: U1.B8@8544.41,7740.63 8563.78,7760 8594,7760 8604,7770 8604,7874 8628,7898 v1(8628,8058)
VP0_VSYNC: U1.D7 U19.7 | length 737.4
  TopLayer w6: U19.7@8473.63,8146.37 8520.25,8193 8610,8193 8646,8157 v1(8646,8029)
  BottomLayer w6: U1.D7@8583.78,7661.89 8603,7681.11 8603,7750 8614,7761 8631,7761 8643,7773 8643,8026 v1(8646,8029)
VP0D2: U1.A9 U19.16 | length 595.3
  TopLayer w6: v1(8545,7816) 8605,7876 8706,7876 8831,8001 8831,8103.58 U19.16@8788.21,8146.37
  BottomLayer w6: U1.A9@8505.04,7780 8505.04,7805.04 8516,7816 v1(8545,7816)
VP0D3: U1.B9 U19.15 | length 595.1
  TopLayer w6: v1(8524,7759.59) 8524,7829 8587,7892 8700,7892 8811,8003 8811,8079.04 U19.15@8765.93,8124.1
  BottomLayer w6: U1.B9@8505.04,7740.63 v1(8524,7759.59)
VP0D4: U1.C9 U19.14 | length 620.7
  TopLayer w6: v1(8485,7721.3) 8485,7816 8578,7909 8695,7909 8787.34,8001.34 8787.34,8058.15 U19.14@8743.66,8101.83
  BottomLayer w6: v1(8485,7721.3) U1.C9@8505.04,7701.26
VP0D5: U1.D9 U19.13 | length 642.5
  TopLayer w6: v1(8485,7681.93) 8467,7699.93 8467,7826 8565,7924 8682,7924 8763.81,8005.81 8763.81,8037.14 U19.13@8721.39,8079.56
  BottomLayer w6: v1(8485,7681.93) U1.D9@8505.04,7661.89
VP0D6: U1.A10 U19.12 | length 479.7
  TopLayer w6: v1(8465.67,7856.67) 8549,7940 8673,7940 8739,8006 8739,8017.41 U19.12@8699.12,8057.29
  BottomLayer w6: U1.A10@8465.67,7780 v1(8465.67,7856.67)
VP0D7: U1.B10 U19.11 | length 145.9
  BottomLayer w6: 8445,7878 8445,7761.3 U1.B10@8465.67,7740.63
VP0D8: U1.C10 U19.10 | length 425.8
  TopLayer w6: v1(8446,7720) 8446,7985.12 U19.10@8540.44,8079.56
  BottomLayer w6: v1(8446,7720) U1.C10@8465.67,7701.26
VP0D9: U1.D10 U19.9 | length 494.6
  TopLayer w6: v1(8445,7682.56) 8426,7701.56 8426,8009.66 U19.9@8518.17,8101.83
  BottomLayer w6: v1(8445,7682.56) U1.D10@8465.67,7661.89
XSPCLK: U1.R5 U22.2
XSPCS: U1.T4 U22.1 | length 307.5
  TopLayer w6: v1(8721.34,7170) 8741.34,7150 8993,7150
  BottomLayer w6: U1.T4@8701.89,7189.45 v1(8721.34,7170)
XSPDI: U1.R4 U22.4 | length 227.6
  TopLayer w6: v1(8721.71,7209) 8741.71,7189 8913,7189
  BottomLayer w6: U1.R4@8701.89,7228.82 v1(8721.71,7209)
XSPDO: U1.P5 U22.3
pads on no net: J1.6 JP3.3 JP3.5 JP4.6 JP4.7 JP4.8 JP6.17 JP6.19 R30.4 R30.5 S2.3 S2.4 U1.A4 U1.A5 U1.A11 U1.A17 U1.AA2 U1.AA3 U1.AA23 U1.AA24 U1.AA25 U1.AA26 U1.AB3 U1.AB11 U1.AB12 U1.AB13 U1.AB14 U1.AB15 U1.AB16 U1.AB23 U1.AB24 U1.AB25 U1.AC1 U1.AC4 U1.AC6 U1.AC7 U1.AC8 U1.AC9 U1.AC10 U1.AC11 U1.AC12 U1.AC13 U1.AC14 U1.AC15 U1.AC16 U1.AC17 U1.AC19 U1.AC20 U1.AC21 U1.AC25 U1.AC26 U1.AD3 U1.AD5 U1.AD6 U1.AD7 U1.AD8 U1.AD9 U1.AD10 U1.AD11 U1.AD12 U1.AD13 U1.AD14 U1.AD15 U1.AD16 U1.AD17 U1.AD19 U1.AD20 U1.AD21 U1.AD22 U1.AD23 U1.AD25 U1.AD26 U1.AE5 U1.AE6 U1.AE7 U1.AE9 U1.AE11 U1.AE15 U1.AE16 U1.AE17 U1.AE18 U1.AE20 U1.AE21 U1.AE22 U1.AE23 U1.AF3 U1.AF4 U1.AF5 U1.AF6 U1.AF8 U1.AF10 U1.AF12 U1.AF14 U1.AF16 U1.AF17 U1.AF18 U1.AF20 U1.AF21 U1.AF23 U1.AF24 U1.B11 U1.B12 U1.B15 U1.B16 U1.B17 U1.C7 U1.C8 U1.C11 U1.C12 U1.C15 U1.C16 U1.C17 U1.D6 U1.D8 U1.D11 U1.D12 U1.D15 U1.D16 U1.D17 U1.E11 U1.E12 U1.E13 U1.E14 U1.L22 U1.M5 U1.M22 U1.N22 U1.P22 U1.R22 U1.R25 U1.R26 U1.T22 U1.T23 U1.W7 U1.W23 U1.W24 U1.Y23 U1.Y24 U1.Y25 U1.Y26 U2.108 U2.113 U2.114 U2.115 U2.116 U2.117 U2.118 U2.119 U2.120 U2.126 U2.127 U2.128 U2.131 U2.138 U2.139 U2.140 U2.141 U2.143 U2.144 U2.152 U2.156 U2.158 U2.159 U2.160 U2.161 U2.162 U2.163 U2.170 U2.175 U2.176 U2.181 U2.182 U2.183 U2.184 U3.B8 U3.H10 U3.J9 U4.1 U6.1 U7.9 U7.10 U7.13 U7.14 U7.15 U7.30 U7.32 U7.34 U7.36 U7.39 U7.41 U7.43 U8.14 U8.30 U8.57 U8.69 U8.70 U8.73 U9.1 U10.1 U10.13 U10.14 U10.16 U10.18 U10.19 U10.20 U10.21 U10.22 U10.23 U10.24 U10.25 U10.26 U10.27 U10.28 U10.29 U10.30 U10.31 U10.33 U10.34 U10.35 U11.1 U14.5 U16.2@5767,9497 U17.2@5029,9740 U19.1 U19.20 U19.22 U19.23 U19.24 U19.26 U19.27 U19.29 U19.34 U19.37 U19.43 U21.1 U22.6 U22.7 U23.1
copper on no net:
  other v3: 4161.02,9198.19 4161.02,9469.84

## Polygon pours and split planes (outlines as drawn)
GND on GROUND (split plane): 4020.01,6020.02 4020.01,9916.99 10278.99,9916.99 10278.99,6020.02

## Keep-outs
KeepOutLayer:
  lines w8: 10240,6222 10240,6119 ; 10240,6119 10240,6319 10240,9619 10090,9619 10090,9819 4240,9819 4240,9619 4065,9619 4065,6319 4240,6319 4240,6119 10090,6119 10240,6119

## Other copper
MidLayer1:
  text ".G1" at 9999,10087 h90
MidLayer2:
  text ".G2" at 9999,10087 h90
MidLayer3:
  text ".G3" at 9999,10087 h90
MidLayer4:
  text ".G4" at 9999,10087 h90
MidLayer5:
  text ".G5" at 9999,10087 h90
MidLayer6:
  text ".G6" at 9999,10087 h90
MidLayer7:
  text ".G7" at 9999,10087 h90
MidLayer8:
  text ".G8" at 9999,10087 h90
BottomLayer:
  region net V5: 7550,9615 7550,9582 7608,9582 7608,9615
  region net V5: 7670,9617 7670,9578 7809,9578 7809,9617
  region net V5: 9386,9596 9003,9596 9003,9544 9386,9544
  region net NetC102_2: 8817,9669 8561,9669 8561,9591 8817,9591
  region net NetC102_2: 8813,9600 8554,9600 8554,9568 8813,9568
  region net GND: 9072,9673 8870,9673 8870,9617 9072,9617
  text "P/N XXXXXX-XXX REV A" at 5320,10137 h75

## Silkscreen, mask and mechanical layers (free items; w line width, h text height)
TopOverlay:
  circle w10: c4140,9717 r112.5
  circle w10: c4140,6217 r112.5
  rectangle: 4281,10340 5031,10540
  rectangle: 4281,10630 5031,10830
  lines w6: 6228,6136 6228,6324 6241,6324 6241,6136 6228,6136 ; 6506,6136 6506,6324 6519,6324 6519,6136 6506,6136
  lines w10: 5392.59,10732.97 ccw(c5441,10772.5) 5392.71,10732.83
  text "C" at 5496,10735 h60
  text "2002 COMPANY NAME" at 5646,10735 h75
  text "S/N" at 4031,10687.5 h75
  text "BOARD NAME" at 5496,10560 h75
  text "ASSY NO.: XXXXXX" at 5496,10410 h75
  text "REV" at 4031,10390 h75
  text "CVBS" at 4148,9231 h60
  text "LVDS OUT" at 4102,8934 h60
  text "LVDS IN" at 4079,7608 h60
  text "FPGA AS MODE" at 6745,6150 h30
BottomOverlay:
  text "LVDS" at 5063,8354 h30
Mechanical1:
  the board outline again, w20
Mechanical4:
  lines w19.68: 10310.04,9162.4 10556.1,9162.4 ; 10311.02,7981.3 10425.2,7981.3 ; 10315.94,9712.6 10562.01,9712.6
  text ".Pcb_File_Name_No_Path" at 8099,10277 h90
  text ".Printout_Name" at 8099,10087 h90
  text "90.45" at 10635.83,9682.09 h60
  text "76.45" at 10638.78,9129.92 h60
  text "46.45" at 10452.76,7801.18 h60

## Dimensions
3980,6217 to 4000,6000 on Mechanical4
4140,5980 to 4000,6000 on Mechanical4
